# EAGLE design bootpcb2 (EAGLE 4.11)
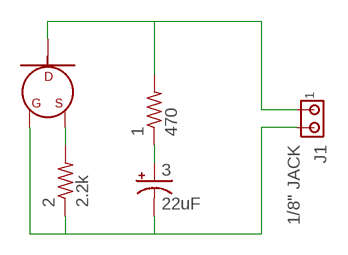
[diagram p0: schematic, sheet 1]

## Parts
1  470  RESISTOR0603-SM  [0603-SM]
2  2.2k  RESISTOR0603-SM  [0603-SM]
3  22uF  CAPACITOR-POL3528-21  [3528-21]
J1  1/8" JACK  JMP/2P/SIPSMT  [PAD/SMT/DUAL]
U$1  MIC/HACK  [MIC/HACK]

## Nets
N$1: 1.P$2 J1.P$1 U$1.P$3
N$2: 1.P$1 3.P$1(+)
N$3: 2.P$2 U$1.P$1
N$4: 2.P$1 3.P$2(-) J1.P$2 U$1.P$2

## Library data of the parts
1 2 = audioint:RESISTOR
3 = audioint:CAPACITOR-POL
J1 = audioint:JMP/2P/SIP
U$1 = audioint:MIC/HACK

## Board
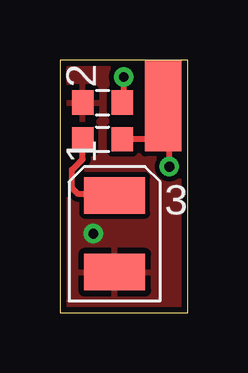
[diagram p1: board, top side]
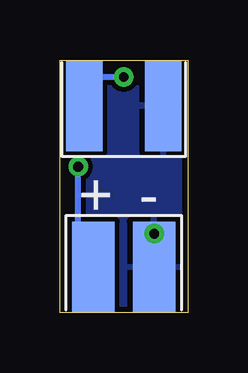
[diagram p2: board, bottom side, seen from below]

Size 5.33 x 10.54 mm. Coordinates in mm from the lower left corner, seen from the top.
Outline: 0,0 5.33,0 5.33,10.54 0,10.54 0,0
Copper layers (1*16): Top 0.035mm / dielectric 1.5mm / Bottom 0.035mm
Design rules "default": minimum track width 10mil, minimum drill 24mil, track to track 8mil, track to pad 8mil, pad to pad 8mil, via to via 8mil, smd to smd 8mil, copper to edge 10mil, drill to drill 8mil, minimum pad ring 10mil, minimum via ring 8mil, stop-mask expansion 4mil, vias tented up to drill 20mil, thermal gap 10mil

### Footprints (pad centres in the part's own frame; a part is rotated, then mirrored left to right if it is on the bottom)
0603-SM = smd 0.889 x 1.016: P$1 -0.826,0; P$2 0.826,0
3528-21 = smd 1.524 x 2.54: P$1 -1.6,0; P$2 1.6,0
PAD/SMT/DUAL = smd 1.778 x 3.81: P$1 -1.27,0; P$2 1.27,0
MIC/HACK = smd 1.524 x 3.81: P$1 -1.651,1.905; P$2 1.651,1.905 | smd 1.524 x 3.81 bottom: P$3 -1.651,1.905

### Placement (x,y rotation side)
1  1.78,7.24 0 top
2  1.78,8.76 0 top
3  2.29,3.3 270 top
J1  2.67,1.91 0 bottom
U$1  2.67,6.73 0 bottom

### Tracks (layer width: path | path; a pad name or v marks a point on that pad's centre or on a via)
N$1  (via drill 0.41 pad 0.81)
  Top 0.254: 1.P$2 4.32,7.24 4.32,8.51 | 4.32,8.51 U$1.P$3 | 4.32,8.51 4.57,8.51 v4.57,6.1
  Bottom 0.254: J1.P$1 4.19,1.91 | 4.19,1.91 4.32,1.91 | 4.19,1.91 4.19,2.03 4.57,2.03 v4.57,6.1
N$2
  Top 0.254: 1.P$1 0.95,6.41 0.51,5.97 0.51,5.21 0.76,4.95 2.29,4.95 3.P$1
N$3  (via drill 0.41 pad 0.81)
  Top 0.254: 2.P$2 2.67,9.02 v2.67,9.83
  Bottom 0.254: U$1.P$1 4.32,9.83 v2.67,9.83
N$4  (via drill 0.41 pad 0.81)
  Bottom 0.254: J1.P$2 v1.4,3.3
  pour Top: 0,0 0,10.54 5.33,10.54 5.33,0
  pour Bottom: 0,10.54 5.33,10.54 5.33,0 0,0

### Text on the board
bPlace: - | +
